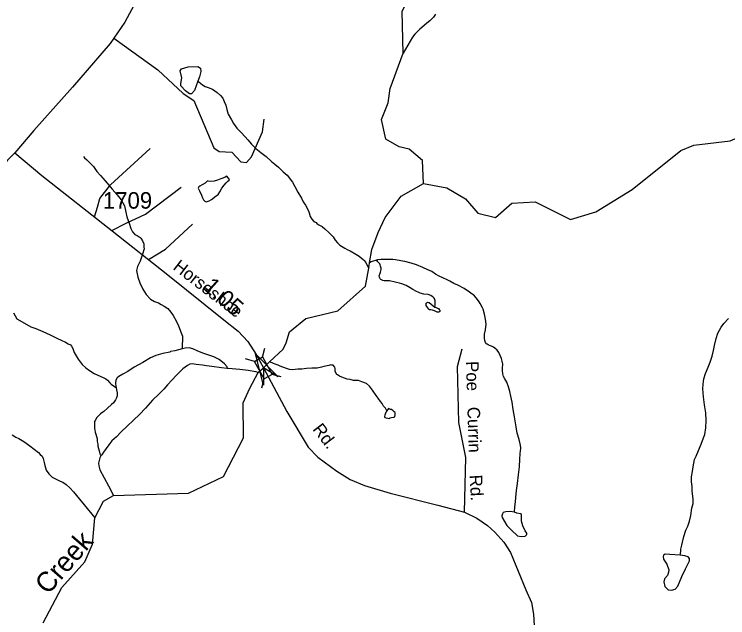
# Model space of a CAD drawing. Extents: x 2056842 to 2160602, y 826753 to 1016856.
# Drawn here: x 2104528 to 2109914, y 850429 to 854986 of the extents above; entities that cross this region are included whole.
import ezdxf

# ---------------------------------------------------------------- set-up
doc = ezdxf.new("R2010")
doc.units = 0
for name, color, linetype in [('Exist Hydrographic Creek Single Shore', 7, 'Continuous'), ('Exist Hydrographic Creek Single Shore Label', 7, 'Continuous'), ('Exist Hydrographic Misc Water Feature', 7, 'Continuous'), ('Exist Road Non-System Type 51', 7, 'Continuous'), ('Exist Road Non-System Type 51 Label', 7, 'Continuous'), ('Exist Road Secondary Mileage Hundredths English Label', 7, 'Continuous'), ('Exist Road Secondary Structure Standard Bridge Attributed CELL', 7, 'Continuous'), ('Exist Road Secondary Structure Standard Bridge CELL', 7, 'Continuous'), ('Exist Road Secondary Type 51 Attributed', 7, 'Continuous'), ('Exist Road Secondary Type 51 Label', 7, 'Continuous'), ('Exist Road Secondary Type 51 Number Label', 7, 'Continuous')]:
    doc.layers.add(name, color=color, linetype=linetype)

msp = doc.modelspace()

# ---------------------------------------------------------------- linework, layer by layer
at = {"layer": 'Exist Hydrographic Creek Single Shore'}
for points in [[(2107465, 854692), (2107455.9, 855007.2), (2107630, 855374.3), (2107720.9, 855500.4), (2108094.9, 855758.5), (2108187.8, 855846.8), (2108236, 855893.4), (2108344, 856052), (2108451.9, 856335.1), (2108556.5, 856612), (2108556.5, 856741.2), (2108527.4, 856852.7), (2108518.6, 856951), (2108541.5, 857002.4), (2108633.4, 857122.7), (2108727.9, 857241.6), (2108939.9, 857470.2), (2108988.9, 857561), (2109048.2, 857657.4)], [(2107349.9, 854317.1), (2107365.9, 854425), (2107465, 854692)], [(2107333.9, 854041.8), (2107299.9, 854190.1), (2107349.9, 854317.1)], [(2107509, 853966), (2107434, 853983.9), (2107333.9, 854041.8)], [(2107617.9, 853707.9), (2107608.9, 853881.9), (2107509, 853966)], [(2104746, 850390.8), (2104886, 850656.9), (2105060.9, 850850.2), (2105117.9, 850983.5), (2105135, 851183.4), (2105201, 851310), (2105276, 851351.1), (2105842, 851369), (2106107.9, 851494.7), (2106258, 851786.9), (2106257, 852052.7), (2106306, 852163.2), (2106367.8, 852281), (2106408.6, 852316.1), (2106455.6, 852361.4), (2106556.9, 852457.5), (2106580, 852505.4), (2106605, 852586.9), (2106730.1, 852689.3), (2106971, 852746.7), (2107178.9, 852932.7), (2107203.4, 853067.7), (2107210.8, 853109.6), (2107226.7, 853210), (2107273.9, 853337.9), (2107327.1, 853451.9), (2107448.7, 853611.5), (2107617.9, 853707.9)]]:
    msp.add_lwpolyline(points, dxfattribs=at)
at = {"layer": 'Exist Hydrographic Misc Water Feature'}
for points in [[(2107709, 854986.6), (2107693, 854964.7), (2107665.2, 854936.9), (2107643.4, 854918.7), (2107621.3, 854900.5), (2107589.3, 854874.5), (2107573.3, 854858.3), (2107551.4, 854836.5), (2107535.4, 854814.1), (2107465, 854692)], [(2105914.6, 854481.3), (2105888.4, 854409.8), (2105866.8, 854385.7), (2105851.6, 854385.7), (2105821.2, 854407.3), (2105785.8, 854445.3), (2105785.8, 854463), (2105793.4, 854504.8), (2105779.5, 854559.3), (2105790.9, 854574.5), (2105840.2, 854589.7), (2105913.7, 854591), (2105932.7, 854578.3), (2105936.5, 854554.2), (2105925.1, 854513.7), (2105914.6, 854481.3)], [(2105914.6, 854481.3), (2105918.7, 854479.2), (2105936.6, 854463.5), (2105948.9, 854453.5), (2105969, 854441.6), (2105991.1, 854433.4), (2106025.4, 854419.6), (2106059.2, 854395.8), (2106084.8, 854371.7), (2106101.6, 854351.7), (2106113.3, 854326), (2106125.2, 854299.8), (2106133.6, 854266.1), (2106143.7, 854232.1), (2106167.9, 854188.3), (2106181.8, 854162.2), (2106207.6, 854126.3), (2106240, 854094.2), (2106271.8, 854060.5), (2106292.1, 854036.4), (2106318.4, 854004.8), (2106352.4, 853972.9), (2106388.3, 853943.1), (2106428.5, 853911.1), (2106470.5, 853875.1), (2106494.7, 853855.1), (2106522.8, 853831.4), (2106558.9, 853795.5), (2106587, 853771.4), (2106627, 853717.4), (2106647.1, 853685.5), (2106669.6, 853641.6), (2106695.9, 853597.8), (2106709.4, 853569.8), (2106725.6, 853543.9), (2106748, 853501.9), (2106753.7, 853486), (2106761.9, 853458), (2106773.8, 853437.9), (2106789.8, 853422.1), (2106806, 853412.4), (2106812.3, 853406.2), (2106825.9, 853396.4), (2106852.1, 853382.3), (2106871.8, 853366.3), (2106906.3, 853334.7), (2106934.4, 853304.5), (2106950.3, 853278.9), (2106968.8, 853258.7), (2106986.4, 853242.6), (2107024.6, 853219), (2107040.8, 853208.9), (2107064.6, 853199.1), (2107107, 853175.3), (2107132.8, 853159.2), (2107163, 853133.5), (2107168.7, 853127.3), (2107183.1, 853111.4), (2107195, 853083.6), (2107203.4, 853067.7)], [(2107617.9, 853707.9), (2107793, 853674.7), (2107934.9, 853593), (2108027, 853482.9), (2108159.9, 853450.6), (2108285, 853559.6), (2108459.9, 853569.1), (2108727, 853435.6), (2108918, 853494), (2109192.9, 853662.2), (2109558.9, 853956.6), (2109658, 853997.1), (2109933, 854030.8), (2110003.1, 854060.6), (2110182.9, 854150.4), (2110366, 854182.7), (2110737.9, 854185.6), (2110866, 854200.7)], [(2105050.7, 853912.8), (2105058.7, 853902.7), (2105074.7, 853886.9), (2105097.1, 853864.8), (2105127, 853835.1), (2105151.2, 853799), (2105179.3, 853767.2), (2105213.6, 853727.1), (2105229.1, 853711.3), (2105265.6, 853665.2), (2105303.8, 853623.3), (2105334.1, 853583.4), (2105360, 853539.8), (2105370.2, 853491.6), (2105377.8, 853455.9), (2105394.4, 853407.9), (2105408.4, 853368.1), (2105420.9, 853343.9), (2105436.7, 853324), (2105454.5, 853316.1), (2105478.5, 853300.3), (2105482.6, 853293.9), (2105496.5, 853276), (2105504.9, 853252), (2105507, 853228.2), (2105508.8, 853214.1), (2105495.1, 853174.4), (2105479.1, 853122.1), (2105457.2, 853079.9), (2105451.2, 853052), (2105459.6, 853000), (2105475.6, 852958.2), (2105497.8, 852910.2), (2105523.8, 852870.2), (2105556, 852834.5), (2105586.3, 852816.5), (2105616.1, 852806.7), (2105636.2, 852794.7), (2105660.2, 852782.6), (2105688.3, 852762.9), (2105710.2, 852736.9), (2105728, 852711), (2105750.8, 852671.1), (2105768.6, 852633.1), (2105788.9, 852581.3), (2105796.9, 852555.4), (2105798.8, 852525.5), (2105795.1, 852493.1), (2105794.9, 852459.5)], [(2105981.3, 853723.6), (2105969.4, 853711.5), (2105945.4, 853697.3), (2105929.4, 853687.6), (2105921.6, 853681.5), (2105915, 853673.6), (2105925.3, 853653.3), (2105941.5, 853619.6), (2105949.5, 853599.4), (2105955.6, 853585.4), (2105967.5, 853575.5), (2105977.6, 853569.5), (2105997.9, 853575.8), (2106017.8, 853587.8), (2106051.8, 853613.9), (2106065.8, 853626), (2106079.3, 853645.8), (2106095.5, 853671.8), (2106111.3, 853696.2), (2106127.3, 853712), (2106141, 853726.1), (2106149.2, 853734.2), (2106153.1, 853738.1), (2106131.4, 853762.1), (2106119.3, 853755.8), (2106103.1, 853748.1), (2106087.1, 853742), (2106062.9, 853731.9), (2106036.8, 853725.7), (2106011.4, 853723.8), (2105990.9, 853725.7), (2105985, 853725.8), (2105981.3, 853723.6)], [(2107255.1, 853127.7), (2107237, 853121.5), (2107222.9, 853115.5), (2107210.8, 853109.6)], [(2108304, 851226.5), (2108306.4, 851265.5), (2108312.1, 851305.1), (2108314.1, 851337.3), (2108320.1, 851389.2), (2108325.8, 851443.5), (2108333.4, 851507.2), (2108341.2, 851569.4), (2108343.5, 851625.4), (2108347.2, 851665.5), (2108348.8, 851691.2), (2108351.3, 851705.4), (2108351.1, 851715.2), (2108346.5, 851741.4), (2108338.5, 851775.5), (2108324.4, 851823.1), (2108316.4, 851869.3), (2108304.3, 851945), (2108294.3, 852000.9), (2108285.6, 852057), (2108275.8, 852103.1), (2108269.7, 852136.9), (2108259.4, 852172.9), (2108247.3, 852206.8), (2108231.3, 852232.8), (2108221.5, 852250.9), (2108215.5, 852270.9), (2108213.1, 852294.8), (2108213.1, 852312.6), (2108215.1, 852342.8), (2108211, 852366.9), (2108205.1, 852386.9), (2108196.9, 852408.8), (2108184.8, 852430.6), (2108172.7, 852450.6), (2108156.7, 852464.4), (2108146.6, 852472.4), (2108130.6, 852478.5), (2108116.3, 852484.4), (2108104.6, 852490.6), (2108096.8, 852494.2), (2108092.5, 852496.4), (2108084.5, 852508.2), (2108080.6, 852522.2), (2108078.5, 852540.4), (2108078.3, 852570.4), (2108084.1, 852602.4), (2108090.2, 852646.5), (2108086.3, 852684.4), (2108077.7, 852722.3), (2108068.1, 852758.2), (2108063.8, 852768.2), (2108045.5, 852802.2), (2108037.3, 852814.4), (2108025.4, 852832), (2108003.3, 852860.1), (2107965.6, 852887.8), (2107923.3, 852915.6), (2107877.2, 852939.7), (2107847.2, 852953.6), (2107815.1, 852969.4), (2107795, 852981.3), (2107763.2, 852995.1), (2107734.9, 853009.1), (2107708.8, 853023.2), (2107679.1, 853043.2), (2107651.2, 853057.1), (2107612.9, 853074.7), (2107564.9, 853092.5), (2107523.1, 853106.5), (2107476.9, 853118.4), (2107447, 853124.2), (2107406.6, 853132.3), (2107384.9, 853134), (2107361.1, 853134), (2107322.7, 853134.1), (2107294.6, 853133.9), (2107271, 853131.8), (2107255.1, 853127.7)], [(2107701.9, 852775.1), (2107704.1, 852793.1), (2107705.8, 852811.1), (2107705.3, 852821.3), (2107703.3, 852829.3), (2107701.9, 852835.2), (2107697.6, 852841.1), (2107689.6, 852849.2), (2107681.8, 852854.9), (2107671.7, 852860.9), (2107653.5, 852868.9), (2107619.6, 852872.8), (2107591.5, 852880.7), (2107577.8, 852886.9), (2107565.5, 852892.8), (2107537.8, 852906.7), (2107517.3, 852918.8), (2107485.3, 852936.5), (2107453.1, 852950.4), (2107435.5, 852956.3), (2107413.1, 852960.1), (2107393.3, 852965.9), (2107369.5, 852970), (2107359.4, 852971.9), (2107345.1, 852972), (2107337.3, 852974), (2107331.5, 852972.1), (2107321.3, 852974), (2107309.6, 852975.8), (2107301.4, 852979.9), (2107295.2, 852983.7), (2107291.1, 852987.9), (2107287, 852993.8), (2107285.4, 853001.7), (2107282.9, 853009.8), (2107285.2, 853017.6), (2107287, 853023.8), (2107293.2, 853037.9), (2107295.2, 853047.7), (2107297.3, 853059.6), (2107297.3, 853067.7), (2107295.2, 853075.7), (2107293.2, 853083.8), (2107290.5, 853093.9), (2107286.8, 853101.8), (2107281.1, 853107.9), (2107269, 853119.9), (2107260.6, 853125.6), (2107255.1, 853127.7)], [(2107701.9, 852775.1), (2107708, 852773), (2107722, 852767.2), (2107729.7, 852763.2), (2107735.9, 852757.4), (2107741.8, 852751.2), (2107741.8, 852747.2), (2107739.6, 852741.4), (2107734.1, 852735.4), (2107730.2, 852735.1), (2107725.9, 852735.4), (2107720.3, 852737.1), (2107699.8, 852747), (2107693.9, 852749.2), (2107686.1, 852751.2), (2107671.5, 852753), (2107663.7, 852755), (2107657.6, 852759.1), (2107650, 852768.8), (2107641.8, 852779), (2107638.1, 852786.9), (2107637.9, 852793), (2107637.7, 852803.1), (2107641.8, 852807), (2107647.5, 852810.9), (2107654.1, 852809.2), (2107660, 852809.1), (2107675.8, 852797), (2107689.8, 852783.1), (2107701.9, 852775.1)], [(2104522.5, 852731.4), (2104546.7, 852685.5), (2104568.5, 852673.3), (2104652.7, 852625.6), (2104690.9, 852611.7), (2104726.8, 852597.8), (2104764.9, 852580.2), (2104803.2, 852562.3), (2104833.2, 852548.4), (2104854.9, 852536.2), (2104881.2, 852524.5), (2104914.8, 852510.4), (2104934.9, 852498.4), (2104951.1, 852488.7), (2104959.3, 852478.6), (2104969.5, 852460.8), (2104979.4, 852430.9), (2105009.7, 852380.9), (2105039.7, 852341), (2105068, 852316.8), (2105095.7, 852295.2), (2105129.9, 852273.4), (2105159.8, 852259.5), (2105199.6, 852243.3), (2105218.1, 852233.6), (2105232, 852223.4), (2105250.1, 852203.6), (2105259.9, 852191.6), (2105269.9, 852185.6), (2105296, 852167.9)], [(2109554.9, 850902.2), (2109559.2, 850929.2), (2109560.9, 850947.2), (2109567.2, 850977.1), (2109573, 850999.3), (2109582.8, 851043.3), (2109597, 851089.4), (2109612.5, 851121.2), (2109624.8, 851157.4), (2109636.5, 851201.5), (2109644.1, 851255.5), (2109652.3, 851291.6), (2109652.3, 851327.3), (2109646, 851383.5), (2109645.6, 851419.3), (2109639.6, 851455.5), (2109641.7, 851493.3), (2109647.6, 851533.4), (2109653.5, 851569.4), (2109659.1, 851595.3), (2109663, 851623.5), (2109674.9, 851649.3), (2109694.6, 851691.4), (2109712.4, 851739.4), (2109730.6, 851787.7), (2109740.1, 851813.5), (2109748.5, 851863.8), (2109752, 851917.6), (2109747.9, 851975.5), (2109737.8, 852035.4), (2109731.3, 852097.7), (2109727.2, 852157.5), (2109729.4, 852193.7), (2109733.1, 852233.7), (2109747.1, 852273.4), (2109766.9, 852321.5), (2109782.5, 852359.7), (2109796.3, 852403.9), (2109806.7, 852445.8), (2109814.3, 852483.9), (2109825.8, 852537.8), (2109840.1, 852577.8), (2109865.8, 852621.8), (2109884, 852651.9), (2109919.7, 852687.9)], [(2105794.9, 852459.5), (2105767.2, 852453.1), (2105739.1, 852445.2), (2105707.3, 852439.1), (2105703.2, 852434.8), (2105649.3, 852424.7), (2105595.2, 852408.6), (2105555.4, 852390.7), (2105497.8, 852356.4), (2105433.6, 852320.3), (2105385.6, 852288.2), (2105347.9, 852267.9), (2105318.1, 852249.7), (2105303.6, 852239.7), (2105294.1, 852223.7), (2105291.9, 852199.7), (2105293.9, 852173.9), (2105296, 852167.9)], [(2106135.5, 852310.5), (2106135.7, 852316.6), (2106133.8, 852322.5), (2106115.2, 852346.5), (2106075.4, 852378), (2106033.4, 852398.2), (2106003.4, 852410), (2105951.1, 852427.7), (2105909.1, 852445.4), (2105875.3, 852459.5), (2105847.2, 852467.4), (2105819.1, 852463.5), (2105794.9, 852459.5)], [(2107340.6, 851990), (2107330.3, 852010.2), (2107316.4, 852026.1), (2107305.9, 852046), (2107292.2, 852061.8), (2107276.2, 852085.8), (2107259.8, 852107.7), (2107232.1, 852147.6), (2107209.7, 852177.7), (2107186, 852197.6), (2107151.7, 852211.3), (2107127.5, 852219.4), (2107103.7, 852219.4), (2107089.6, 852221.1), (2107063.3, 852227.1), (2107041.6, 852231.3), (2107021.7, 852237.1), (2106999.6, 852244.9), (2106983.6, 852253), (2106975.8, 852257.1), (2106967.8, 852262.7), (2106963.9, 852264.9), (2106949.5, 852289), (2106949.5, 852300.8), (2106949.3, 852310.9), (2106947.3, 852321), (2106935.6, 852335), (2106925.3, 852336.9), (2106917.5, 852338.9), (2106903.2, 852334.6), (2106865.2, 852326.5), (2106847.4, 852320.7), (2106815.4, 852314.6), (2106773.4, 852312.5), (2106733.4, 852310.4), (2106699.6, 852306.2), (2106667.6, 852305.8), (2106647.5, 852304), (2106631.3, 852301.9), (2106606.3, 852302.9), (2106582.2, 852311.8), (2106535.1, 852329.5), (2106519.1, 852335.5), (2106497.6, 852343.3), (2106485.5, 852349.6), (2106475, 852353.6), (2106455.6, 852361.4)], [(2106135.5, 852310.5), (2106091.6, 852316.4), (2106019.6, 852326.1), (2105979.8, 852331.6), (2105947.6, 852335.7), (2105901.5, 852341.5), (2105869.5, 852345.5), (2105853.3, 852343.5), (2105835.5, 852333.2), (2105799.6, 852309.4), (2105751.6, 852261.1), (2105717.8, 852223.3), (2105684.1, 852187), (2105656.3, 852154.7), (2105620.4, 852118.7), (2105570.3, 852072.8), (2105518.7, 852012.4), (2105472.7, 851964.2), (2105335.2, 851832), (2105299.1, 851793.7), (2105265.4, 851765.9), (2105241.4, 851733.5), (2105221.3, 851707.7), (2105201.9, 851679.4), (2105187.9, 851659.6), (2105182, 851651.6)], [(2106367.8, 852281), (2106351.4, 852285.1), (2106293.6, 852294.7), (2106231.6, 852302.8), (2106141.4, 852310.4), (2106135.5, 852310.5)], [(2105296, 852167.9), (2105300.1, 852149.8), (2105304.6, 852127.6), (2105304.4, 852103.7), (2105300.3, 852089.7), (2105292.1, 852073.9), (2105276.5, 852051.5), (2105262.8, 852039.8), (2105232.4, 852011.6), (2105203.1, 851985.6), (2105178.7, 851969.4), (2105150.6, 851941.2), (2105138.9, 851919.4), (2105134.6, 851911.5), (2105133.4, 851885.3), (2105133.2, 851861.5), (2105139.1, 851831.3), (2105153.3, 851781.3), (2105153.1, 851759.4), (2105157.4, 851739.3), (2105159.6, 851725.1), (2105163.5, 851707.5), (2105167.8, 851689.4), (2105173.6, 851665.4), (2105182, 851651.6)], [(2107340.6, 851990), (2107330.1, 851974.1), (2107324.6, 851957.9), (2107322.5, 851948.1), (2107324.4, 851942.1), (2107334.8, 851938.1), (2107348.6, 851936), (2107362.7, 851934.3), (2107362.5, 851938.3), (2107374.6, 851940.2), (2107390.6, 851944.2), (2107396.5, 851944.1), (2107400.2, 851948.4), (2107404.3, 851960.4), (2107404.3, 851968.1), (2107402.3, 851978.2), (2107396.5, 851984.3), (2107388.5, 851990.4), (2107376.2, 852000.4), (2107368.4, 852002.4), (2107352.5, 852008.1), (2107340.6, 851990)], [(2104511.3, 851809.2), (2104539.1, 851793.6), (2104561.5, 851781.7), (2104599.4, 851759.7), (2104645.6, 851728), (2104677.3, 851702.1), (2104709.5, 851676.1), (2104723.9, 851662.1), (2104737.6, 851648.3), (2104745.6, 851632.1), (2104747.9, 851620), (2104754, 851600.4), (2104758.3, 851578.2), (2104768, 851542.2), (2104788.5, 851516.5), (2104800.6, 851502.5), (2104814.3, 851490.2), (2104838.1, 851478.5), (2104854.3, 851470.4), (2104874.2, 851460.4), (2104894.3, 851452.5), (2104918.9, 851434.6), (2104946.8, 851410.9), (2104974.5, 851378.7), (2104998.7, 851353.1), (2105135, 851183.4)], [(2105182, 851651.6), (2105173.8, 851635.4), (2105167.8, 851615.6), (2105164.1, 851595.5), (2105166.2, 851575.3), (2105174, 851545.7), (2105239.1, 851423.7), (2105276, 851351.1)], [(2108304, 851226.5), (2108272.3, 851230.3), (2108239.4, 851227.8), (2108219.1, 851222.7), (2108214.1, 851213.9), (2108207.7, 851198.7), (2108210.3, 851184.7), (2108247, 851126.4), (2108281.2, 851089.7), (2108326.7, 851047.9), (2108354.6, 851042.8), (2108383.7, 851045.4), (2108396.4, 851056.8), (2108396.4, 851066.9), (2108383.7, 851084.6), (2108367.3, 851123.9), (2108357.1, 851156.9), (2108357.1, 851189.8), (2108357.1, 851208.8), (2108350.8, 851213.9), (2108321.7, 851218.9), (2108304, 851226.5)], [(2109554.9, 850902.2), (2109477.7, 850906), (2109441, 850908.5), (2109428.3, 850900.9), (2109425.8, 850892.1), (2109429.6, 850871.8), (2109453.6, 850833.8), (2109470.1, 850789.4), (2109467.6, 850773), (2109458.7, 850747.6), (2109437.2, 850722.3), (2109430.8, 850699.5), (2109439.7, 850665.3), (2109465, 850638.7), (2109490.4, 850636.1), (2109516.9, 850645), (2109538.5, 850666.6), (2109567.6, 850740), (2109594.2, 850797), (2109625.8, 850859.1), (2109624.6, 850876.9), (2109614.4, 850888.3), (2109589.1, 850897.1), (2109554.9, 850902.2)]]:
    msp.add_lwpolyline(points, dxfattribs=at)
at = {"layer": 'Exist Road Non-System Type 51'}
for points in [[(2105279, 854805), (2105612.7, 854565.7), (2105801.7, 854387), (2105882.7, 854335), (2106035.4, 853976.5), (2106074.8, 853949.5), (2106170.4, 853943.3), (2106238.9, 853872.6), (2106280.5, 853866.4), (2106317.8, 853910), (2106403, 854099.1), (2106413.4, 854192.7)], [(2105132.8, 853457), (2105155.8, 853528.6), (2105174.4, 853595.1), (2105255.4, 853697), (2105552.5, 853971.3)], [(2105264.1, 853354.2), (2105371.8, 853408.1), (2105519.2, 853476.6), (2105787.2, 853680.3)], [(2105541.8, 853133.8), (2105668.8, 853212.7), (2105872.3, 853399.7)], [(2107927.8, 851226.6), (2107935.8, 851638.3), (2107882.9, 851903.3), (2107874.6, 852325.2), (2107909.9, 852458.2)]]:
    msp.add_lwpolyline(points, dxfattribs=at)
at = {"layer": 'Exist Road Secondary Structure Standard Bridge Attributed CELL'}
msp.add_lwpolyline([(2106410.5, 852186.1), (2106347.8, 852421.8), (2106519.9, 852249), (2106408.6, 852316.1)], close=True, dxfattribs=at)
at = {"layer": 'Exist Road Secondary Structure Standard Bridge CELL'}
for p, q in [((2106401.2, 852397.5), (2106420, 852463.9)), ((2106340.9, 852363.9), (2106274.6, 852382.7)), ((2106542.3, 852247.4), (2106475.9, 852266.2)), ((2106395.5, 852165.4), (2106414.3, 852231.8))]:
    msp.add_line(p, q, dxfattribs=at)
msp.add_lwpolyline([(2106414.3, 852231.8), (2106340.7, 852363.7), (2106402.3, 852398.1), (2106475.9, 852266.2)], close=True, dxfattribs=at)
at = {"layer": 'Exist Road Secondary Type 51 Attributed'}
for points in [[(2106245.9, 857063.8), (2106236.6, 857029.8), (2106183.1, 856876.6), (2106067.3, 856567.4), (2105929.2, 856233.8), (2105781.2, 855865.4), (2105611.5, 855455.5), (2105448.9, 855085), (2105362.8, 854927.1), (2105251.1, 854764.4), (2104968.1, 854436.6), (2104675.8, 854108.7), (2104531, 853939.9)], [(2104531, 853939.9), (2104475.4, 853884.3), (2104195, 853532), (2103957.7, 853202.1), (2103804, 852968.2), (2103711.1, 852856.5), (2103487.8, 852631), (2103224.1, 852394.1), (2102716.8, 851951.9), (2102478.5, 851730.1), (2102423.4, 851670.8), (2102358, 851531.6), (2102161.2, 851006.3), (2102003.9, 850573.5), (2101953, 850487.2)], [(2104531, 853939.9), (2104736, 853767.9), (2105267.2, 853351.7), (2105688.3, 853017.6), (2106110.4, 852678.3), (2106218.4, 852593.1), (2106292.2, 852515.2), (2106355, 852415.9), (2106408.6, 852316.1)], [(2106408.6, 852316.1), (2106586.6, 851985.7), (2106746, 851717.1), (2106820.7, 851640.2), (2106963, 851536.3), (2107063.7, 851471.8), (2107171.2, 851427.7), (2107364.4, 851368.5), (2107725.2, 851279.6), (2107927.7, 851226.6), (2108019.1, 851181.9), (2108101.1, 851124.8), (2108156.2, 851073.8), (2108224.2, 851000.6), (2108274, 850922.7), (2108389.8, 850638.4), (2108432.4, 850543.9), (2108446.9, 850455.5), (2108453.5, 850370.5)]]:
    msp.add_lwpolyline(points, dxfattribs=at)

# ---------------------------------------------------------------- texts
at = {"layer": 'Exist Hydrographic Creek Single Shore Label'}
msp.add_text('Creek', height=150, rotation=49.0844, dxfattribs=at).set_placement((2104783, 850596.4))
at = {"layer": 'Exist Road Non-System Type 51 Label'}
for s, rotation, p in [('Poe', 271.8345, (2107937.3, 852365.4)), ('Currin', 271.8345, (2107948.2, 852020)), ('Rd.', 273.0471, (2107965, 851506.3))]:
    msp.add_text(s, height=95, rotation=rotation, dxfattribs=at).set_placement(p)
at = {"layer": 'Exist Road Secondary Mileage Hundredths English Label'}
msp.add_text('1.05', height=125, rotation=318.1576, dxfattribs=at).set_placement((2105945.7, 852916.9))
at = {"layer": 'Exist Road Secondary Type 51 Label'}
for s, rotation, p in [('Horseshoe', 322.2999, (2105719.6, 853064.9)), ('Rd.', 307.4439, (2106775.5, 851851.1))]:
    msp.add_text(s, height=95, rotation=rotation, dxfattribs=at).set_placement(p)
at = {"layer": 'Exist Road Secondary Type 51 Number Label'}
msp.add_text('1709', height=125, dxfattribs=at).set_placement((2105196.8, 853517.8))

doc.saveas('drawing.dxf')
